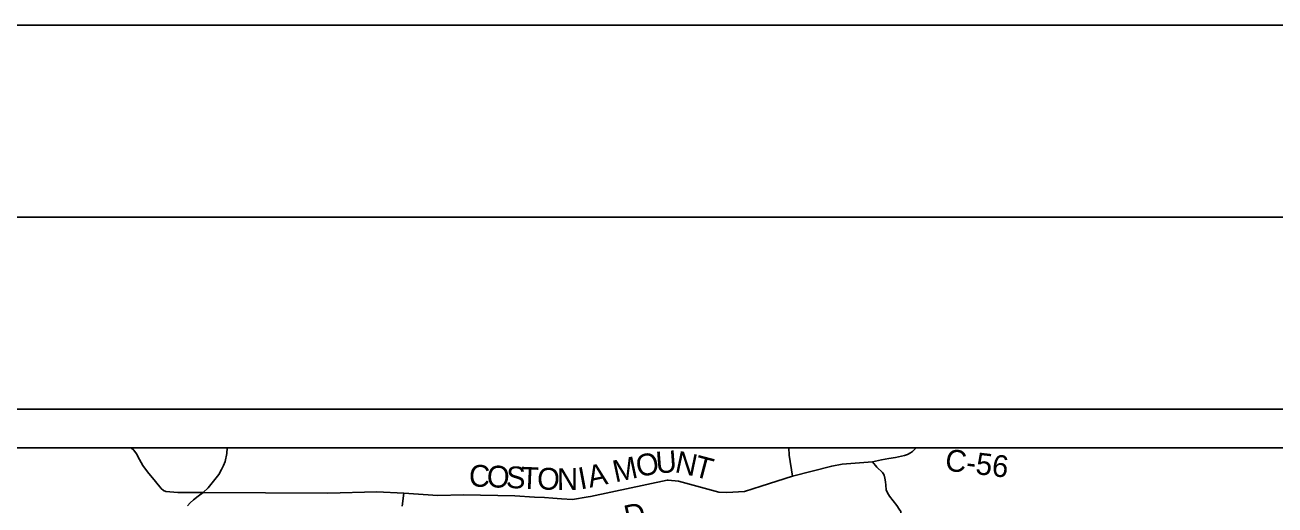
# Model space of a CAD drawing. Extents: x 0 to 34, y 0 to 22.
# Drawn here: x 4.685 to 7.939, y 20.751 to 22 of the extents above; entities that cross this region are included whole.
import ezdxf

# ---------------------------------------------------------------- set-up
doc = ezdxf.new("R2010")
doc.units = 0
for name, color, linetype in [('GM_X_County_Road', 7, 'Continuous'), ('GM_X_County_Road_Text', 7, 'Continuous'), ('GM_X_State_Route', 7, 'Continuous'), ('GM_X_Township_Road', 7, 'Continuous'), ('SH_Border', 7, 'Continuous'), ('SH_Cut_Line', 7, 'Continuous'), ('SH_Data', 7, 'Continuous')]:
    doc.layers.add(name, color=color, linetype=linetype)

msp = doc.modelspace()

# ---------------------------------------------------------------- linework, layer by layer
at = {"layer": 'GM_X_County_Road'}
msp.add_line((6.1574, 20.7734), (6.3566, 20.8152), dxfattribs=at)
for points in [[(4.9619, 20.9), (4.9688, 20.8935), (4.9752, 20.8843), (4.9832, 20.8693), (4.9921, 20.8536), (5.0044, 20.837), (5.0246, 20.812), (5.0396, 20.794), (5.0458, 20.789), (5.0522, 20.7862), (5.0832, 20.7837), (5.1491, 20.7832)], [(6.3566, 20.8152), (6.3595, 20.8158), (6.3866, 20.8128), (6.4909, 20.7847), (6.5122, 20.7831), (6.5583, 20.7859), (6.6018, 20.7996), (6.6827, 20.8261), (6.7854, 20.8521), (6.8119, 20.8568), (6.8913, 20.863), (6.9149, 20.8684), (6.9338, 20.872), (6.9509, 20.8748), (6.9746, 20.88), (6.982, 20.8827), (6.9899, 20.8867), (6.9952, 20.8903), (7.0028, 20.8976), (7.0048, 20.9)], [(5.1491, 20.7832), (5.4734, 20.7821), (5.6011, 20.7848), (5.671, 20.7813), (5.7602, 20.7755), (5.8269, 20.7773), (5.9601, 20.7748), (6.0116, 20.7717), (6.0377, 20.7703), (6.0592, 20.7689), (6.0817, 20.767), (6.1101, 20.7655), (6.1515, 20.7722), (6.1574, 20.7734)]]:
    msp.add_lwpolyline(points, dxfattribs=at)
at = {"layer": 'GM_X_State_Route'}
msp.add_lwpolyline([(5.1085, 20.7491), (5.1156, 20.7566), (5.124, 20.7643), (5.1362, 20.7741), (5.1491, 20.7832), (5.1622, 20.7956), (5.1758, 20.8133), (5.1896, 20.8306), (5.1968, 20.8434), (5.202, 20.854), (5.2063, 20.8639), (5.2104, 20.8847), (5.2114, 20.9)], dxfattribs=at)
at = {"layer": 'GM_X_Township_Road'}
for points in [[(6.6827, 20.8261), (6.6747, 20.8805), (6.6734, 20.9)], [(6.9673, 20.6747), (6.9661, 20.7252), (6.9651, 20.7339), (6.9609, 20.7404), (6.9549, 20.7493), (6.9452, 20.7615), (6.9352, 20.7743), (6.9302, 20.7824), (6.9271, 20.7905), (6.9263, 20.8027), (6.9251, 20.8114), (6.9236, 20.8208), (6.9214, 20.8286), (6.9193, 20.8325), (6.917, 20.8358), (6.9028, 20.8495), (6.8913, 20.863)], [(5.6666, 20.7478), (5.671, 20.7813)]]:
    msp.add_lwpolyline(points, dxfattribs=at)
at = {"layer": 'SH_Border'}
msp.add_lwpolyline([(1.5, 21.5), (33.5, 21.5), (33.5, 0.5), (1.5, 0.5)], close=True, dxfattribs=at)
at = {"layer": 'SH_Cut_Line'}
msp.add_lwpolyline([(0, 0), (34, 0), (34, 22), (0, 22)], close=True, dxfattribs=at)
at = {"layer": 'SH_Data'}
msp.add_line((2, 21), (9, 21), dxfattribs=at)
msp.add_lwpolyline([(2.1, 20.9), (8.9, 20.9), (8.9, 14.1), (2.1, 14.1)], close=True, dxfattribs=at)

# ---------------------------------------------------------------- texts
at = {"layer": 'GM_X_County_Road_Text'}
for s, height, rotation, p in [('U', 0.0568, 4.3389, (6.329, 20.8327)), ('N', 0.0568, 348.0121, (6.3746, 20.8368)), ('C-56', 0.05682, 353.2897, (7.0783, 20.8409)), ('C', 0.0568, 357.5405, (5.8399, 20.7996)), ('A', 0.0568, 11.7324, (6.1554, 20.7957)), ('M', 0.0568, 12.0961, (6.2218, 20.8096)), ('O', 0.0568, 12.0444, (6.2821, 20.8226)), ('T', 0.0568, 345.2362, (6.4228, 20.8265)), ('O', 0.0568, 357.5404, (5.8865, 20.7976)), ('S', 0.0568, 357.5381, (5.9364, 20.7955)), ('T', 0.0568, 357.5396, (5.9747, 20.7938)), ('O', 0.0568, 357.5887, (6.0173, 20.792)), ('N', 0.0568, 0.3041, (6.0702, 20.7899)), ('I', 0.0568, 10.6165, (6.1313, 20.7912)), ('D', 0.0568, 12.2862, (6.2517, 20.6925))]:
    msp.add_text(s, height=height, rotation=rotation, dxfattribs=at).set_placement(p)

doc.saveas('drawing.dxf')
